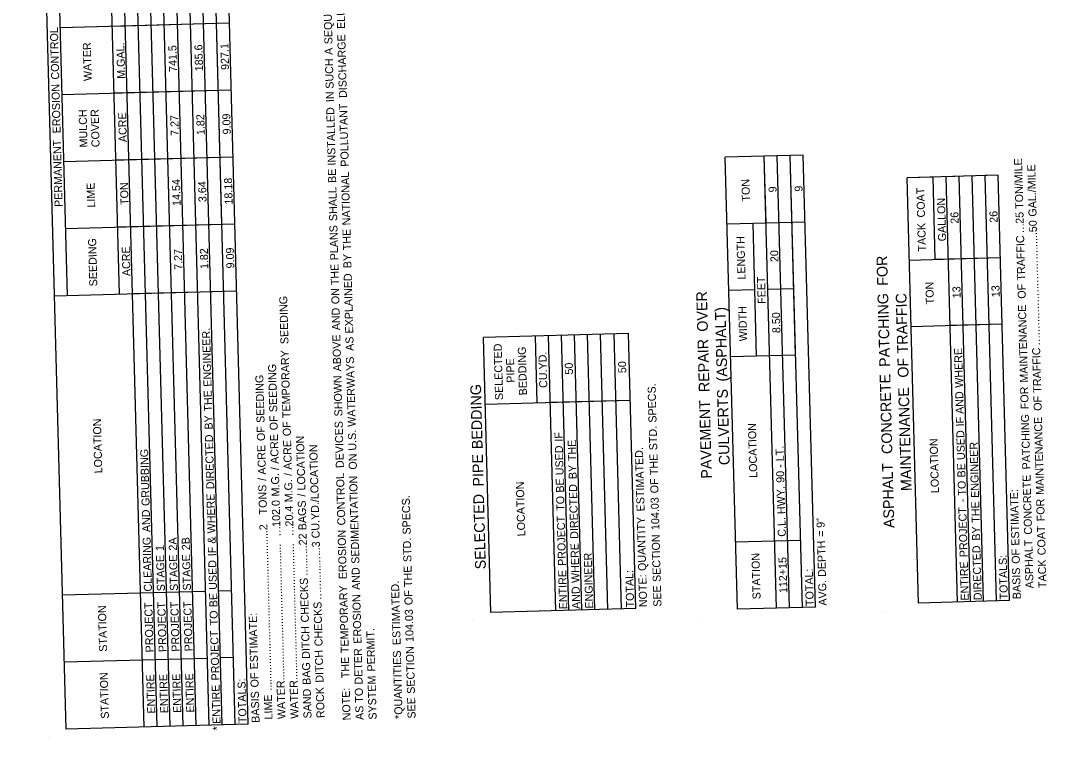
# Model space of a CAD drawing. Extents: x 1930091 to 1931962, y 596452 to 607874.
# Drawn here: x 1930332 to 1931101, y 599203 to 599740 of the extents above; entities that cross this region are included whole.
import ezdxf

# ---------------------------------------------------------------- set-up
doc = ezdxf.new("R2010")
doc.units = 0
doc.layers.add('Default', color=7, linetype='Continuous')
doc.layers.add('R_Border', color=7, linetype='Continuous')

msp = doc.modelspace()

# ---------------------------------------------------------------- linework, layer by layer
at = {"layer": 'Default'}
for p, q in [((1930434.12, 599211.25), (1930399.9, 600486.09)), ((1930443.87, 599211.51), (1930409.65, 600486.35)), ((1930453.61, 599211.78), (1930419.39, 600486.62)), ((1930463.36, 599212.04), (1930429.14, 600486.88)), ((1930473.11, 599212.3), (1930438.88, 600487.14)), ((1930482.85, 599212.56), (1930448.63, 600487.4)), ((1930492.6, 599212.82), (1930458.38, 600487.66)), ((1930502.35, 599213.08), (1930468.12, 600487.92)), ((1930365.9, 599209.42), (1930331.67, 600484.26)), ((1930366.93, 599534.24), (1930341.42, 600484.52)), ((1930405.92, 599535.29), (1930380.41, 600485.57)), ((1930424.37, 599210.99), (1930390.15, 600485.83)), ((1930482.54, 599587.57), (1930476.64, 599807.36)), ((1930488.24, 599738.42), (1930361.54, 599735.02)), ((1930478.5, 599738.16), (1930400.53, 599736.06)), ((1930489.59, 599688.23), (1930362.89, 599684.82)), ((1930479.84, 599687.96), (1930401.87, 599685.87)), ((1930490.94, 599638.03), (1930364.23, 599634.63)), ((1930481.19, 599637.77), (1930403.22, 599635.68)), ((1930918.33, 599639.54), (1930859.85, 599637.97)), ((1930918.33, 599639.54), (1930859.85, 599637.97)), ((1930868.94, 599299.28), (1930859.85, 599637.97)), ((1930898.18, 599300.07), (1930889.09, 599638.76)), ((1930890.44, 599588.57), (1930889.09, 599638.76)), ((1930907.93, 599300.33), (1930898.84, 599639.02)), ((1930917.67, 599300.59), (1930908.58, 599639.28)), ((1930912.6, 599489.67), (1930908.58, 599639.28)), ((1930927.42, 599300.85), (1930918.33, 599639.54)), ((1931064.3, 599624.44), (1930996.07, 599622.61)), ((1931015.56, 599623.13), (1930996.07, 599622.61)), ((1931004.63, 599303.9), (1930996.07, 599622.61)), ((1931017.23, 599561.24), (1931015.56, 599623.13)), ((1931044.8, 599623.92), (1931025.31, 599623.39)), ((1931033.87, 599304.68), (1931025.31, 599623.39)), ((1931043.61, 599304.95), (1931035.06, 599623.66)), ((1931053.36, 599305.21), (1931044.8, 599623.92)), ((1931064.3, 599624.44), (1931054.55, 599624.18)), ((1931063.11, 599305.47), (1931054.55, 599624.18)), ((1931072.85, 599305.73), (1931064.3, 599624.44)), ((1930492.29, 599587.84), (1930365.58, 599584.44)), ((1930492.29, 599587.84), (1930404.57, 599585.48)), ((1930919.68, 599589.35), (1930861.2, 599587.78)), ((1930883.36, 599488.89), (1930880.69, 599588.3)), ((1930883.36, 599488.89), (1930880.69, 599588.3)), ((1930909.93, 599589.09), (1930890.44, 599588.57)), ((1931065.96, 599562.55), (1930997.73, 599560.72)), ((1931065.96, 599562.55), (1931017.23, 599561.24)), ((1930493.63, 599537.64), (1930357.18, 599533.98)), ((1930464.39, 599536.86), (1930415.66, 599535.55)), ((1930493.63, 599537.64), (1930474.14, 599537.12)), ((1930882.02, 599538.6), (1930862.53, 599538.07)), ((1930911.26, 599539.38), (1930891.77, 599538.86)), ((1930911.26, 599539.38), (1930891.77, 599538.86)), ((1931067.29, 599512.84), (1930999.07, 599511.01)), ((1931067.29, 599512.84), (1931028.31, 599511.8)), ((1930787.29, 599505.88), (1930678.62, 599502.97)), ((1930787.29, 599505.88), (1930678.62, 599502.97)), ((1930684.15, 599296.83), (1930678.62, 599502.97)), ((1930718.95, 599453.82), (1930717.6, 599504.01)), ((1930732.88, 599298.14), (1930727.35, 599504.27)), ((1930742.63, 599298.4), (1930737.1, 599504.54)), ((1930752.38, 599298.66), (1930746.84, 599504.8)), ((1930762.12, 599298.92), (1930756.59, 599505.06)), ((1930771.87, 599299.18), (1930766.34, 599505.32)), ((1930782.1, 599299.46), (1930776.57, 599505.6)), ((1930792.83, 599299.75), (1930787.29, 599505.88)), ((1930912.6, 599489.67), (1930863.87, 599488.37)), ((1930912.6, 599489.67), (1930893.11, 599489.15)), ((1930788.64, 599455.69), (1930679.97, 599452.77)), ((1930788.64, 599455.69), (1930728.7, 599454.08)), ((1930916.33, 599350.79), (1930867.59, 599349.48)), ((1930916.33, 599350.79), (1930896.83, 599350.26)), ((1930470.41, 599312.69), (1930363.2, 599309.81)), ((1930470.41, 599312.69), (1930421.68, 599311.38)), ((1930489.9, 599313.21), (1930480.16, 599312.95)), ((1930489.9, 599313.21), (1930480.16, 599312.95)), ((1931072.85, 599305.73), (1931004.63, 599303.9)), ((1931072.85, 599305.73), (1931004.63, 599303.9)), ((1930792.83, 599299.75), (1930684.15, 599296.83)), ((1930792.83, 599299.75), (1930684.15, 599296.83)), ((1930927.42, 599300.85), (1930868.94, 599299.28)), ((1930927.42, 599300.85), (1930868.94, 599299.28)), ((1930471.76, 599262.49), (1930364.55, 599259.62)), ((1930471.76, 599262.49), (1930423.03, 599261.19)), ((1930491.25, 599263.02), (1930481.51, 599262.76)), ((1930491.25, 599263.02), (1930481.51, 599262.76)), ((1930502.35, 599213.08), (1930365.9, 599209.42)), ((1930502.35, 599213.08), (1930365.9, 599209.42))]:
    msp.add_line(p, q, dxfattribs=at)
at = {"layer": 'R_Border'}
for p, q in [((1930977.49, 599297.32), (1930977.49, 599297.32)), ((1930670.66, 599290.61), (1930670.66, 599290.61)), ((1930841.81, 599292.7), (1930841.81, 599292.7)), ((1930352.41, 599203.21), (1930352.41, 599203.21))]:
    msp.add_line(p, q, dxfattribs=at)

# ---------------------------------------------------------------- texts
at = {"layer": 'Default'}
for s, height, p in [(' ELIMINATION', 6, (1930575, 599731.95)), (' SEQUENCE', 6, (1930565.55, 599720.47)), (' CONTROL', 6, (1930360.76, 599694.03)), (' DISCHARGE', 6, (1930576.39, 599680.24)), ('WATER', 6, (1930385.12, 599695.18)), ('M.GAL.', 6, (1930410.13, 599696.82)), ('741.5', 6, (1930449.01, 599701.93)), ('185.6', 6, (1930468.5, 599702.48)), ('927.1', 6, (1930487.98, 599703.49)), (' A', 6, (1930565.77, 599712.54)), (' SUCH', 6, (1930566.45, 599687.14)), (' EROSION', 6, (1930361.85, 599653.73)), (' IN', 6, (1930566.72, 599677.12)), ('MULCH', 6, (1930381.95, 599645.4)), ('COVER', 6, (1930390.95, 599645.57)), ('ACRE', 6, (1930411.41, 599649.34)), (' INSTALLED', 6, (1930567.99, 599629.6)), (' POLLUTANT', 6, (1930577.77, 599628.72)), ('7.27', 6, (1930450.29, 599654.09)), ('1.82', 6, (1930469.79, 599654.64)), ('9.09', 6, (1930489.28, 599655.14)), ('PERMANENT', 6, (1930363.27, 599600.81)), (' TON/MILE', 6, (1931083.34, 599597.16)), (' BE', 6, (1930568.34, 599616.54)), (' NATIONAL', 6, (1930578.95, 599584.78)), (' GAL./MILE', 6, (1931093.25, 599591.29)), ('LIME', 6, (1930387.66, 599600.33)), ('TON', 6, (1930412.67, 599602.3)), ('14.54', 6, (1930451.7, 599601.58)), ('3.64', 6, (1930471.13, 599604.43)), ('18.18', 6, (1930490.69, 599602.61)), ('TON', 6, (1930878.37, 599604.84)), (' SHALL', 6, (1930569.11, 599587.96)), ('9', 6, (1930898.37, 599611.75)), ('9', 6, (1930917.86, 599612.28)), (' COAT', 6, (1931009.68, 599590.69)), ('GALLON', 6, (1931025.41, 599575.06)), ('26', 6, (1931034.81, 599588.21)), ('26', 6, (1931064.05, 599588.95)), ('25', 6, (1931083.58, 599588.18)), (' PLANS', 6, (1930569.9, 599558.59)), ('TACK', 6, (1931010.31, 599567.42)), ('…', 6, (1931083.77, 599580.78)), ('.....50', 6, (1931093.8, 599570.74)), (' THE', 6, (1930579.45, 599566.14)), (' TRAFFIC', 6, (1931084.78, 599543.4)), ('SEEDING', 6, (1930389.25, 599541.33)), ('LENGTH', 6, (1930875.06, 599546.36)), ('ACRE', 6, (1930414.1, 599548.95)), ('7.27', 6, (1930452.99, 599553.7)), ('1.82', 6, (1930472.48, 599554.25)), ('9.09', 6, (1930491.97, 599554.75)), (' BY', 6, (1930579.81, 599552.69)), ('20', 6, (1930899.77, 599559.48)), (' FOR', 8, (1930981.84, 599538.78)), ('…', 6, (1931094, 599563.35)), (' THE', 6, (1930570.4, 599539.94)), ('…', 6, (1931094.19, 599555.95)), (' EXPLAINED', 6, (1930581.12, 599503.77)), ('FEET', 6, (1930890.18, 599528.18)), ('…', 6, (1931094.39, 599548.55)), ('…', 6, (1931094.59, 599541.16)), ('TON', 6, (1931016.25, 599527.83)), ('13', 6, (1931036.31, 599532.41)), ('13', 6, (1931065.55, 599533.19)), (' OF', 6, (1931085.14, 599529.82)), ('…', 6, (1931094.79, 599533.76)), (' SEEDING', 6, (1930532.57, 599495.77)), (' ON', 6, (1930570.78, 599525.73)), (' OVER', 8, (1930846.95, 599504.39)), (' PATCHING', 8, (1930983.47, 599478)), (' TRAFFIC', 8, (1930996.86, 599488.07)), ('…', 6, (1931094.99, 599526.36)), (' (ASPHALT)', 8, (1930861.61, 599467.03)), ('WIDTH', 6, (1930876.3, 599500.15)), (' MAINTENANCE', 6, (1931086.83, 599466.94)), ('…', 6, (1931095.19, 599518.97)), (' AND', 6, (1930571.31, 599506.16)), ('8.50', 6, (1930901.2, 599506.28)), ('…', 6, (1931095.39, 599511.57)), ('…', 6, (1931095.58, 599504.17)), (' ENGINEER.', 6, (1930474.91, 599463.88)), (' ABOVE', 6, (1930572.13, 599475.39)), (' AS', 6, (1930581.47, 599490.7)), ('…', 6, (1931095.78, 599496.78)), ('SELECTED', 6, (1930693.38, 599456.08)), ('BEDDING', 6, (1930711.29, 599459.64)), (' REPAIR', 8, (1930848.17, 599459.12)), (' WHERE', 6, (1931038.17, 599463.09)), (' TRAFFIC', 6, (1931096.79, 599459.4)), (' TEMPORARY', 6, (1930534.06, 599440.42)), (' WATERWAYS', 6, (1930583, 599433.87)), ('PIPE', 6, (1930702.04, 599469.13)), ('CU.YD.', 6, (1930726.52, 599465.21)), (' OF', 8, (1930997.34, 599469.97)), (' SEEDING', 6, (1930524.19, 599444.82)), ('50', 6, (1930745.76, 599475.19)), ('50', 6, (1930785.72, 599476.27)), (' SEEDING', 6, (1930514.65, 599436.76)), (' SHOWN', 6, (1930573.04, 599441.63)), (' CONCRETE', 8, (1930985.22, 599412.74)), (' BEDDING', 8, (1930678.12, 599416.38)), (' SPECS.', 6, (1930808.42, 599436.93)), ('CULVERTS', 8, (1930863.21, 599407.35)), ('MAINTENANCE', 8, (1930999.54, 599387.96)), (' FOR', 6, (1931087.36, 599447.04)), (' THE', 6, (1930475.41, 599445.24)), (' AND', 6, (1931038.69, 599443.51)), (' OF', 6, (1931097.15, 599445.82)), ('PAVEMENT', 8, (1930849.83, 599397.26)), ('LOCATION', 6, (1930393.01, 599401.21)), (' BY', 6, (1930475.77, 599431.79)), (' OF', 6, (1930524.55, 599431.24)), (' IF', 6, (1931038.94, 599434.12)), (' PATCHING', 6, (1931088.58, 599401.93)), (' MAINTENANCE', 6, (1931098.84, 599382.94)), (' OF', 6, (1930515.01, 599423.18)), (' OF', 6, (1930534.42, 599426.83)), (' DEVICES', 6, (1930574.08, 599402.94)), (' U.S.', 6, (1930583.48, 599415.97)), (' STD.', 6, (1930808.98, 599416.25)), ('LOCATION', 6, (1930883.93, 599397.85)), (' USED', 6, (1931039.62, 599408.96)), (' DIRECTED', 6, (1930476.97, 599387.07)), (' ACRE', 6, (1930525.23, 599406.07)), (' ACRE', 6, (1930535.1, 599401.67)), (' LOCATION', 6, (1930545.27, 599386.16)), (' IF', 6, (1930738.09, 599422.72)), (' THE', 6, (1930748.24, 599408.09)), ('LOCATION', 6, (1931020.04, 599386.38)), (' GRUBBING', 6, (1930428.54, 599374.48)), (' ACRE', 6, (1930515.69, 599398.01)), (' CU.YD./LOCATION', 6, (1930555.98, 599350.23)), (' USED', 6, (1930738.77, 599397.55)), (' ESTIMATED.', 6, (1930799.48, 599370.46)), (' LT.', 6, (1930903.84, 599408)), (' ENGINEER', 6, (1931050.13, 599380.63)), (' ON', 6, (1930583.86, 599401.76)), (' PIPE', 8, (1930678.87, 599388.37)), (' THE', 6, (1930809.48, 599397.6)), (' /', 6, (1930525.35, 599401.41)), (' BY', 6, (1930748.6, 599394.64)), (' 90', 6, (1930904.27, 599391.9)), (' -', 6, (1930903.97, 599403.14)), ('ASPHALT', 8, (1930986.63, 599360.2)), (' BE', 6, (1931039.97, 599395.9)), (' /', 6, (1930515.81, 599393.35)), (' M.G.', 6, (1930525.88, 599381.66)), (' /', 6, (1930535.22, 599397.01)), (' M.G.', 6, (1930535.75, 599377.26)), (' CONTROL', 6, (1930575.23, 599359.94)), (' SEDIMENTATION', 6, (1930585.76, 599331.2)), ('LOCATION', 6, (1930710, 599353.99)), (' BE', 6, (1930739.12, 599384.49)), (' OF', 6, (1930809.85, 599384.02)), (' TO', 6, (1931040.34, 599382.31)), (' CONCRETE', 6, (1931089.89, 599353.02)), (' TONS', 6, (1930516.49, 599368.18)), (' DIRECTED', 6, (1930749.8, 599349.93)), (' HWY.', 6, (1930904.9, 599368.43)), (' ESTIMATE:', 6, (1931080.36, 599344.77)), (' WHERE', 6, (1930477.86, 599354)), ('102.0', 6, (1930526.43, 599361.1)), (' /', 6, (1930545.39, 599381.5)), (' BAGS', 6, (1930546.07, 599356.32)), (' SPECS.', 6, (1930624.18, 599353.12)), ('SELECTED', 8, (1930680.45, 599329.31)), (' TO', 6, (1930739.48, 599370.9)), (' 104.03', 6, (1930810.59, 599356.46)), (' -', 6, (1931040.47, 599377.45)), (' THE', 6, (1931050.63, 599361.99)), (' FOR', 6, (1931099.37, 599363.03)), (' AND', 6, (1930429.06, 599354.9)), ('20.4', 6, (1930536.18, 599361.37)), (' PROJECT', 6, (1931041.57, 599336.17)), (' PROJECT', 6, (1930740.59, 599329.63)), (' QUANTITY', 6, (1930800.68, 599325.83)), (' C.L.', 6, (1930905.35, 599351.47)), (' 9"', 6, (1930934.44, 599358.16)), (' ......................................................2', 6, (1930520.04, 599235.99)), ('…', 6, (1930526.63, 599353.71)), ('…', 6, (1930536.38, 599353.97)), ('..22', 6, (1930546.43, 599342.79)), (' EROSION', 6, (1930576.31, 599319.65)), (' =', 6, (1930934.62, 599351.41)), (' BY', 6, (1931050.99, 599348.54)), (' COAT', 6, (1931100.06, 599337.59)), ('CLEARING', 6, (1930430.2, 599312.58)), (' 2A', 6, (1930448.94, 599341.07)), (' 2B', 6, (1930458.69, 599341.33)), (' &', 6, (1930478.06, 599346.27)), (' WATER..............................................', 6, (1930540.11, 599215.07)), ('..3', 6, (1930556.22, 599341.3)), (' STD.', 6, (1930624.74, 599332.44)), (' WHERE', 6, (1930750.69, 599316.85)), (' SECTION', 6, (1930811.63, 599317.56)), (' DEPTH', 6, (1930935.42, 599321.35)), ('ASPHALT', 6, (1931090.91, 599314.99)), (' 1', 6, (1930439.2, 599340.81)), (' IF', 6, (1930478.32, 599336.88)), (' WATER..............................................', 6, (1930530.36, 599214.81)), ('…', 6, (1930546.63, 599335.4)), ('…', 6, (1930556.42, 599333.9)), ('ENGINEER', 6, (1930760.9, 599299.86)), ('STATION', 6, (1930886.37, 599306.8)), ('DIRECTED', 6, (1931052.13, 599306.15)), (' OF', 6, (1931080.72, 599331.19)), ('STAGE', 6, (1930439.95, 599312.85)), ('STAGE', 6, (1930449.69, 599313.11)), ('STAGE', 6, (1930459.44, 599313.37)), (' USED', 6, (1930478.99, 599311.72)), ('..', 6, (1930546.74, 599331.47)), ('..', 6, (1930556.53, 599329.98)), ('112+15', 6, (1930906.43, 599311.47)), ('ENTIRE', 6, (1931042.39, 599305.89)), ('TOTALS:', 6, (1931071.63, 599306.67)), ('TACK', 6, (1931100.66, 599315.25)), ('…', 6, (1930546.93, 599324.08)), ('…', 6, (1930556.73, 599322.58)), (' AND', 6, (1930586.28, 599311.63)), (' THE', 6, (1930625.24, 599313.8)), ('ENTIRE', 6, (1930741.41, 599299.34)), ('TOTAL:', 6, (1930791.6, 599300.69)), ('TOTAL:', 6, (1930926.19, 599301.8)), ('BASIS', 6, (1931081.37, 599306.93)), (' CHECKS', 6, (1930547.92, 599287.26)), ('.', 6, (1930556.77, 599320.99)), ('…', 6, (1930556.97, 599313.59)), (' ESTIMATED.', 6, (1930616.65, 599270.28)), ('NOTE:', 6, (1930801.35, 599300.95)), ('AVG.', 6, (1930935.94, 599302.06)), (' BE', 6, (1930479.34, 599298.66)), ('…', 6, (1930557.17, 599306.19)), (' TEMPORARY', 6, (1930577.8, 599264.29)), (' EROSION', 6, (1930587.36, 599271.34)), (' OF', 6, (1930625.6, 599300.21)), ('AND', 6, (1930751.15, 599299.6)), ('SEE', 6, (1930812.07, 599301.24)), ('PROJECT', 6, (1930431.42, 599267.04)), ('PROJECT', 6, (1930441.17, 599267.3)), ('PROJECT', 6, (1930450.92, 599267.56)), ('PROJECT', 6, (1930460.66, 599267.82)), (' CHECKS', 6, (1930558.16, 599269.38)), ('STATION', 6, (1930396.6, 599267.52)), (' TO', 6, (1930479.71, 599285.07)), (' ESTIMATE:', 6, (1930509.85, 599252.12)), (' 104.03', 6, (1930626.34, 599272.65)), (' PROJECT', 6, (1930480.81, 599243.79)), (' DITCH', 6, (1930548.65, 599260)), (' PERMIT.', 6, (1930597.68, 599250.48)), (' DITCH', 6, (1930558.89, 599242.12)), (' DETER', 6, (1930588.19, 599240.72)), ('*QUANTITIES', 6, (1930618.08, 599217.17)), (' SECTION', 6, (1930627.39, 599233.75)), (' BAG', 6, (1930549.18, 599240.5)), ('   THE', 6, (1930578.42, 599241)), ('STATION', 6, (1930397.94, 599217.33)), ('ENTIRE', 6, (1930432.65, 599221.17)), ('ENTIRE', 6, (1930442.4, 599221.44)), ('ENTIRE', 6, (1930452.15, 599221.7)), ('ENTIRE', 6, (1930461.89, 599221.96)), (' OF', 6, (1930510.22, 599238.54)), ('SYSTEM', 6, (1930598.59, 599216.64)), ('ENTIRE', 6, (1930481.63, 599213.5)), ('TOTALS:', 6, (1930501.12, 599214.03)), (' ROCK', 6, (1930559.6, 599215.6)), ('BASIS', 6, (1930510.87, 599214.29)), (' LIME', 6, (1930520.61, 599214.55)), (' SAND', 6, (1930549.85, 599215.33)), ('NOTE:', 6, (1930579.09, 599216.12)), (' TO', 6, (1930588.55, 599227.12)), ('SEE', 6, (1930627.82, 599217.43)), ('AS', 6, (1930588.84, 599216.38)), ('*', 6, (1930481.76, 599208.59))]:
    msp.add_text(s, height=height, rotation=91.53769, dxfattribs=at).set_placement(p)

doc.saveas('drawing.dxf')
